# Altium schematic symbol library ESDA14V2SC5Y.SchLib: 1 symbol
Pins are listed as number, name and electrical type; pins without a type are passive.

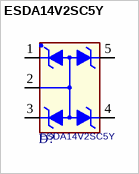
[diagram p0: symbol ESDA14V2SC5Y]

## ESDA14V2SC5Y
designator D?
footprint ST_SOT23-5L
pins: 1, 2, 3, 4, 5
